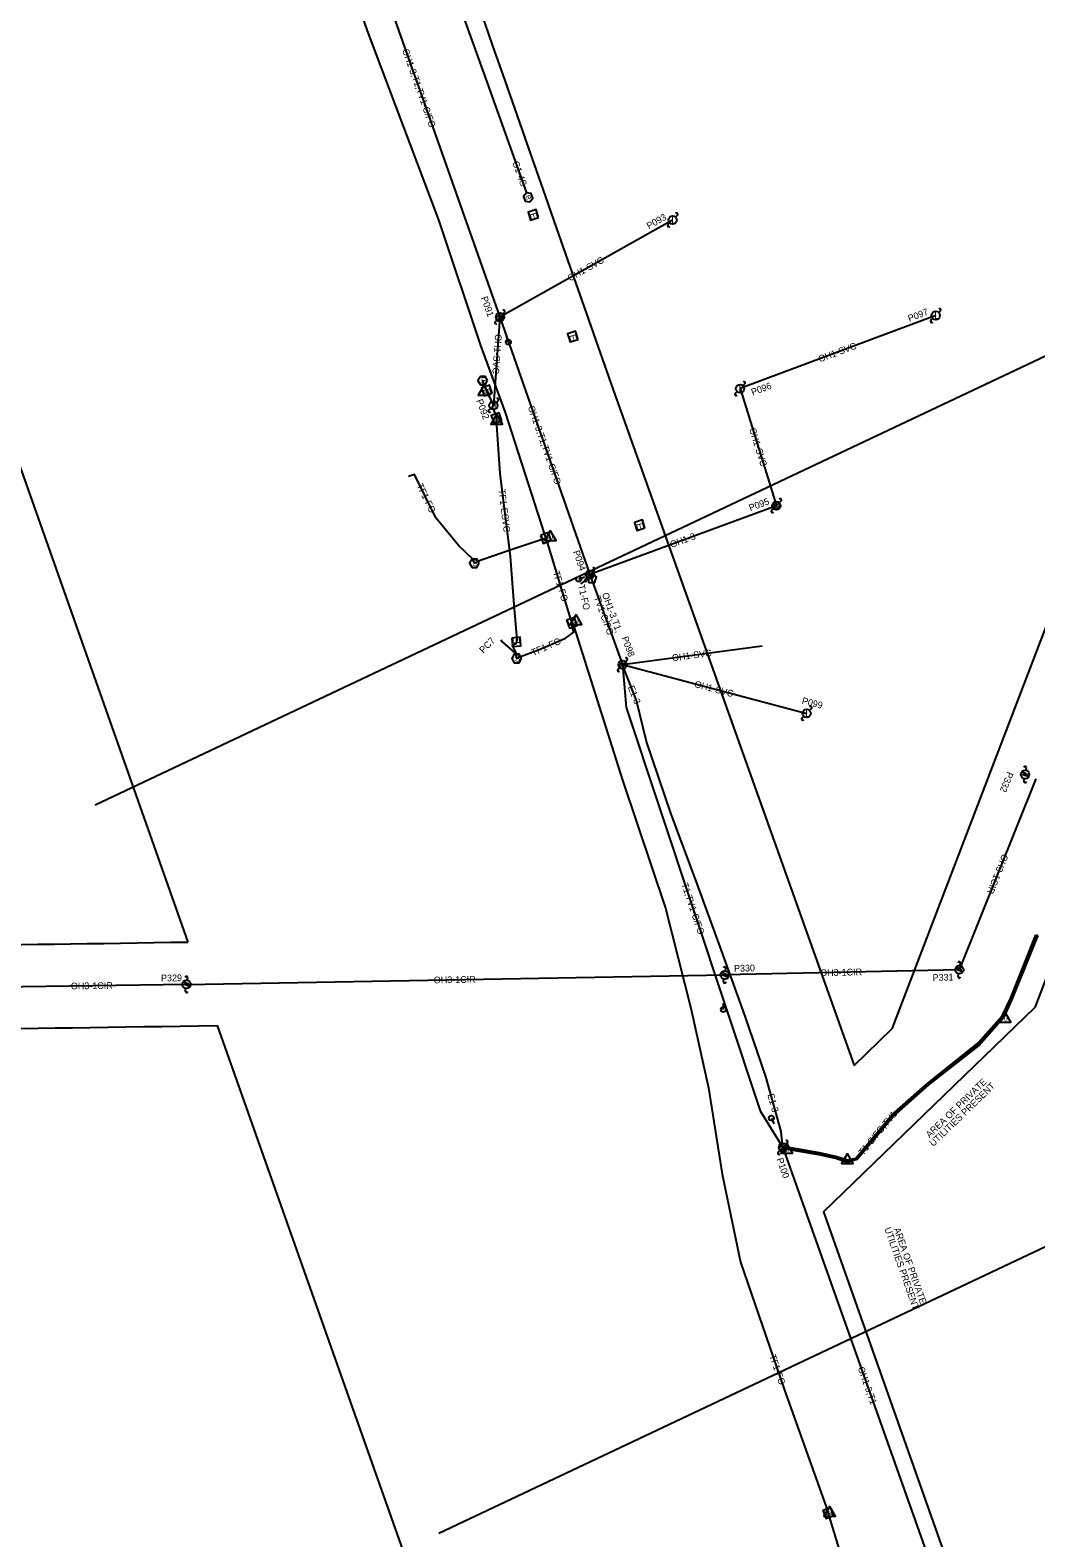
# Model space of a CAD drawing. Extents: x 1991878 to 2008544, y 770238 to 1141211.
# Drawn here: x 2005581 to 2006181, y 1137047 to 1137946 of the extents above; entities that cross this region are included whole.
import ezdxf

# ---------------------------------------------------------------- set-up
doc = ezdxf.new("R2010")
doc.units = 0
for name, color, linetype in [('RD_EX_SU_Elec', 7, 'Continuous'), ('RD_EX_SU_Gas', 7, 'Continuous'), ('RD_EX_SU_Misc', 7, 'Continuous'), ('RD_EX_SU_Ovhd', 7, 'Continuous'), ('RD_EX_SU_Pole', 7, 'Continuous'), ('RD_EX_SU_SwpLmt', 7, 'Continuous'), ('RD_EX_SU_Telecom', 7, 'Continuous'), ('RD_EX_SU_Trfc', 7, 'Continuous'), ('RD_EX_SU_TX_Elec', 7, 'Continuous'), ('RD_EX_SU_TX_Gas', 7, 'Continuous'), ('RD_EX_SU_TX_Misc', 7, 'Continuous'), ('RD_EX_SU_TX_Ovhd', 7, 'Continuous'), ('RD_EX_SU_TX_Pole', 7, 'Continuous'), ('RD_EX_SU_TX_Telecom', 7, 'Continuous'), ('RD_EX_SU_TX_Trfc', 7, 'Continuous'), ('RD_HC_Cl', 7, 'Continuous')]:
    doc.layers.add(name, color=color, linetype=linetype)

# ---------------------------------------------------------------- blocks, each defined once
blk = doc.blocks.new('GW')
at = {"layer": 'RD_EX_SU_Pole'}
blk.add_line((0, 0), (0, 5), dxfattribs=at)
blk.add_circle((0, 0), 2, dxfattribs=at)

msp = doc.modelspace()

# ---------------------------------------------------------------- linework, layer by layer
at = {"layer": 'RD_EX_SU_Elec'}
for points in [[(2005884.55, 1137834.25), (2005883.1, 1137839.03), (2005878.32, 1137837.59), (2005879.77, 1137832.8)], [(2005908.05, 1137761.71), (2005906.6, 1137766.5), (2005901.82, 1137765.05), (2005903.27, 1137760.27)], [(2005854.13, 1137737.14), (2005852.69, 1137739.63), (2005849.8, 1137739.63), (2005848.36, 1137737.14), (2005849.8, 1137734.64), (2005852.69, 1137734.64)], [(2005856.85, 1137729.6), (2005855.21, 1137734.32), (2005850.49, 1137732.68), (2005852.13, 1137727.96)], [(2005862.67, 1137713.21), (2005861.03, 1137717.93), (2005856.31, 1137716.29), (2005857.95, 1137711.57)], [(2005947.98, 1137649.3), (2005946.54, 1137654.09), (2005941.75, 1137652.64), (2005943.2, 1137647.86)], [(2005868.56, 1137583.69), (2005868.98, 1137578.71), (2005873.96, 1137579.13), (2005873.54, 1137584.11)]]:
    msp.add_lwpolyline(points, close=True, dxfattribs=at)
for points in [[(2005851.24, 1137737.14), (2005851.38, 1137736.57), (2005853.08, 1137731.64), (2005853.67, 1137731.14), (2005853.7, 1137730.29), (2005857.16, 1137723.18), (2005857.61, 1137722.35), (2005856.88, 1137721.34), (2005859.2, 1137716.04), (2005859.49, 1137714.75), (2005859.21, 1137713.5), (2005861.45, 1137681.78), (2005867.49, 1137632.27), (2005869.8, 1137603.46), (2005871.55, 1137582.69), (2005871.26, 1137581.41), (2005870.87, 1137580.22), (2005868.76, 1137579.27), (2005871.05, 1137574.94), (2005871.43, 1137571.49)], [(2006030.23, 1137280.03), (2006029.93, 1137281.33), (2006029.09, 1137289.62), (2006020, 1137322.26), (2006007.75, 1137358.28), (2005993.52, 1137397.42), (2005979.03, 1137437.19), (2005963.36, 1137479.35), (2005948.86, 1137522.07), (2005942.96, 1137546.51), (2005934.89, 1137566.81), (2005934.61, 1137567.83)]]:
    msp.add_lwpolyline(points, dxfattribs=at)
at = {"layer": 'RD_EX_SU_Gas'}
msp.add_lwpolyline([(2005837.69, 1137959.33), (2005854.61, 1137912.37), (2005871.82, 1137864.61), (2005877.34, 1137849.07)], dxfattribs=at)
msp.add_lwpolyline([(2005879.27, 1137843.63), (2005881.15, 1137845.83), (2005880.18, 1137848.55), (2005877.34, 1137849.07), (2005875.47, 1137846.87), (2005876.44, 1137844.15)], close=True, dxfattribs=at)
at = {"layer": 'RD_EX_SU_Misc'}
for points in [[(2005852, 1137734.38), (2005848.53, 1137728.38), (2005855.46, 1137728.38)], [(2005859.51, 1137717.1), (2005856.04, 1137711.1), (2005862.97, 1137711.1)], [(2005891.47, 1137647.76), (2005888.01, 1137641.76), (2005894.94, 1137641.76)], [(2005906.85, 1137597.8), (2005903.39, 1137591.8), (2005910.32, 1137591.8)], [(2006162.65, 1137360.82), (2006159.18, 1137354.82), (2006166.11, 1137354.82)], [(2006032.44, 1137282.75), (2006028.98, 1137276.75), (2006035.91, 1137276.75)], [(2006068.69, 1137276.47), (2006065.22, 1137270.47), (2006072.15, 1137270.47)], [(2006058.14, 1137066.23), (2006054.67, 1137060.23), (2006061.6, 1137060.23)]]:
    msp.add_lwpolyline(points, close=True, dxfattribs=at)
at = {"layer": 'RD_EX_SU_Ovhd'}
for p, q in [((2005765.34, 1138046.91), (2005861.45, 1137774.95)), ((2005964.48, 1137832.84), (2005861.45, 1137774.95)), ((2005861.45, 1137774.95), (2005857.61, 1137722.35)), ((2005861.45, 1137774.95), (2005915.09, 1137621.47)), ((2006121.36, 1137775.91), (2006004.67, 1137732.36)), ((2006004.67, 1137732.36), (2006026.31, 1137662.56)), ((2006026.31, 1137662.56), (2005915.09, 1137621.47)), ((2005915.09, 1137621.47), (2005934.61, 1137567.83)), ((2005934.61, 1137567.83), (2006017.9, 1137579.03)), ((2005934.61, 1137567.83), (2006044.4, 1137538.79)), ((2006181.07, 1137499.76), (2006135.42, 1137385.97)), ((2005674.58, 1137377.24), (2005995.53, 1137382.92)), ((2006135.42, 1137385.97), (2005995.53, 1137382.92)), ((2005674.58, 1137377.24), (2005562.69, 1137375.66)), ((2006030.23, 1137280.03), (2006130.7, 1136997.12))]:
    msp.add_line(p, q, dxfattribs=at)
msp.add_lwpolyline([(2005934.61, 1137567.83), (2005936.8, 1137542.22), (2006016.65, 1137301.86), (2006030.23, 1137280.03)], dxfattribs=at)
at = {"layer": 'RD_EX_SU_Pole'}
for p, q in [((2005966.25, 1137834.61), (2005967.31, 1137835.67)), ((2005961.66, 1137830.01), (2005962.72, 1137831.07)), ((2005863.21, 1137776.72), (2005864.27, 1137777.78)), ((2006123.13, 1137777.67), (2006124.19, 1137778.73)), ((2005858.62, 1137772.12), (2005859.68, 1137773.18)), ((2005859.03, 1137774.3), (2005862.09, 1137777.36)), ((2005859.68, 1137773.18), (2005863.21, 1137776.72)), ((2005860.8, 1137772.53), (2005863.86, 1137775.59)), ((2006118.53, 1137773.08), (2006119.59, 1137774.14)), ((2006006.44, 1137734.13), (2006007.5, 1137735.19)), ((2005859.37, 1137724.12), (2005860.43, 1137725.18)), ((2006001.85, 1137729.53), (2006002.91, 1137730.59)), ((2005854.78, 1137719.52), (2005855.84, 1137720.58)), ((2006023.89, 1137661.91), (2006026.95, 1137664.97)), ((2006024.54, 1137660.79), (2006028.07, 1137664.32)), ((2006025.66, 1137660.14), (2006028.72, 1137663.2)), ((2006028.07, 1137664.32), (2006029.13, 1137665.38)), ((2006023.48, 1137659.73), (2006024.54, 1137660.79)), ((2005912.27, 1137618.65), (2005913.33, 1137619.71)), ((2005912.68, 1137620.83), (2005915.74, 1137623.89)), ((2005913.33, 1137619.71), (2005916.86, 1137623.24)), ((2005914.45, 1137619.06), (2005917.51, 1137622.12)), ((2005916.86, 1137623.24), (2005917.92, 1137624.3)), ((2005931.79, 1137565), (2005932.85, 1137566.06)), ((2005932.2, 1137567.19), (2005935.26, 1137570.25)), ((2005932.85, 1137566.06), (2005936.38, 1137569.6)), ((2005933.97, 1137565.42), (2005937.03, 1137568.48)), ((2005936.38, 1137569.6), (2005937.44, 1137570.66)), ((2006041.58, 1137535.97), (2006042.64, 1137537.03)), ((2006046.17, 1137540.56), (2006047.23, 1137541.62)), ((2006173.96, 1137498.4), (2006174.22, 1137499.88)), ((2006175.12, 1137504.8), (2006175.39, 1137506.27)), ((2005995.98, 1137385.38), (2005996.24, 1137386.85)), ((2006134.71, 1137382.04), (2006134.97, 1137383.51)), ((2006135.87, 1137388.43), (2006136.14, 1137389.91)), ((2005673.87, 1137373.3), (2005674.13, 1137374.78)), ((2005675.03, 1137379.7), (2005675.3, 1137381.17)), ((2005994.81, 1137378.98), (2005995.08, 1137380.46)), ((2006027.4, 1137277.2), (2006028.46, 1137278.26)), ((2006027.81, 1137279.38), (2006030.87, 1137282.44)), ((2006028.46, 1137278.26), (2006032, 1137281.8)), ((2006029.58, 1137277.61), (2006032.64, 1137280.68)), ((2006032, 1137281.8), (2006033.06, 1137282.86))]:
    msp.add_line(p, q, dxfattribs=at)
for points in [[(2006173.2, 1137503.77), (2006175.03, 1137502.58), (2006173.37, 1137502.41), (2006176.44, 1137501.27), (2006176.44, 1137501.27), (2006174.26, 1137502.31), (2006175.86, 1137502.44)], [(2005994.06, 1137384.35), (2005995.89, 1137383.16), (2005994.23, 1137382.99), (2005997.3, 1137381.85), (2005997.3, 1137381.85), (2005995.12, 1137382.89), (2005996.71, 1137383.02)], [(2006133.95, 1137387.4), (2006135.78, 1137386.21), (2006134.12, 1137386.04), (2006137.19, 1137384.91), (2006137.19, 1137384.91), (2006135.01, 1137385.95), (2006136.61, 1137386.07)], [(2005673.11, 1137378.67), (2005674.94, 1137377.48), (2005673.28, 1137377.31), (2005676.35, 1137376.17), (2005676.35, 1137376.17), (2005674.17, 1137377.21), (2005675.77, 1137377.34)]]:
    msp.add_lwpolyline(points, close=True, dxfattribs=at)
for centre in [(2005964.48, 1137832.84), (2006121.36, 1137775.91), (2005861.45, 1137774.95), (2006004.67, 1137732.36), (2005857.61, 1137722.35), (2006026.31, 1137662.56), (2005915.09, 1137621.47), (2005934.61, 1137567.83), (2006044.4, 1137538.79), (2006174.67, 1137502.34), (2005995.53, 1137382.92), (2006135.42, 1137385.97), (2005674.58, 1137377.24), (2006030.23, 1137280.03)]:
    msp.add_circle(centre, 2.5, dxfattribs=at)
for centre, start, end in [((2005966.78, 1137836.2), 315.01158, 135.01158), ((2005962.19, 1137829.48), 135.01158, 315.01158), ((2005863.74, 1137778.31), 315.01158, 135.01158), ((2006123.66, 1137779.26), 315.01158, 135.01158), ((2005859.15, 1137771.59), 135.01158, 315.01158), ((2006119.06, 1137772.55), 135.01158, 315.01158), ((2006006.97, 1137735.72), 315.01158, 135.01158), ((2005859.9, 1137725.71), 315.01158, 135.01158), ((2006002.38, 1137729), 135.01158, 315.01158), ((2005855.31, 1137718.99), 135.01158, 315.01158), ((2006028.6, 1137665.92), 315.01158, 135.01158), ((2006024.01, 1137659.2), 135.01158, 315.01158), ((2005917.39, 1137624.83), 315.01158, 135.01158), ((2005912.8, 1137618.11), 135.01158, 315.01158), ((2005936.91, 1137571.19), 315.01158, 135.01158), ((2005932.32, 1137564.47), 135.01158, 315.01158), ((2006042.11, 1137535.43), 135.01158, 315.01158), ((2006046.7, 1137542.15), 315.01158, 135.01158), ((2006174.65, 1137506.41), 349.68899, 169.68899), ((2006174.69, 1137498.27), 169.68899, 349.68899), ((2005995.51, 1137386.99), 349.68899, 169.68899), ((2006135.4, 1137390.04), 349.68899, 169.68899), ((2005674.56, 1137381.31), 349.68899, 169.68899), ((2005995.55, 1137378.85), 169.68899, 349.68899), ((2006135.44, 1137381.9), 169.68899, 349.68899), ((2005674.6, 1137373.17), 169.68899, 349.68899), ((2006032.53, 1137283.39), 315.01158, 135.01158), ((2006027.93, 1137276.67), 135.01158, 315.01158)]:
    msp.add_arc(centre, 0.75, start, end, dxfattribs=at)
at = {"layer": 'RD_EX_SU_SwpLmt'}
for p, q in [((2005030.01, 1139228.23), (2005675.36, 1137402.49)), ((2006541.57, 1138517.27), (2006095.16, 1137350.72)), ((2006396.36, 1137927.97), (2006180.36, 1137363.51)), ((2005928.75, 1137732.27), (2006072.69, 1137329)), ((2006054.36, 1137241.77), (2006180.36, 1137363.51)), ((2005692.93, 1137352.77), (2006786.69, 1134258.45)), ((2006072.69, 1137329), (2006095.16, 1137350.72)), ((2006054.36, 1137241.77), (2006432.49, 1136172))]:
    msp.add_line(p, q, dxfattribs=at)
for points in [[(2005533.64, 1138832.03), (2005572.71, 1138741.34), (2005634.23, 1138568.62), (2005740.87, 1138268.93), (2005928.75, 1137732.27)], [(2005029.38, 1137367.89), (2005225.74, 1137395.38), (2005285.84, 1137396.55), (2005358.1, 1137397.97), (2005567.61, 1137400.8), (2005675.36, 1137402.49)], [(2005046.71, 1137319.82), (2005231.01, 1137345.47), (2005288.28, 1137346.59), (2005359.52, 1137347.99), (2005574.44, 1137350.89), (2005692.93, 1137352.77)]]:
    msp.add_open_spline(points, degree=3, dxfattribs=at)
for points in [[(2004646.84, 1138135.19), (2004687.52, 1138023.2), (2004923.72, 1137366.12), (2005034.36, 1137059.95), (2005190.27, 1136632.11), (2005397.95, 1136061.46), (2006006.55, 1134389.96)], [(2005046.71, 1137319.82), (2005128.36, 1137094.06), (2005284.23, 1136666.33), (2005491.91, 1136095.67), (2006159.4, 1134262.44)]]:
    msp.add_spline(points, degree=3, dxfattribs=at)
at = {"layer": 'RD_EX_SU_Telecom'}
msp.add_lwpolyline([(2005916.31, 1137622.29), (2005913.45, 1137620.21), (2005914.54, 1137616.86), (2005918.07, 1137616.86), (2005919.16, 1137620.21)], close=True, dxfattribs=at)
for points in [[(2005915.09, 1137621.47), (2005915.7, 1137620.79), (2005916.16, 1137619.73), (2005916.31, 1137619.29)], [(2006030.23, 1137280.03), (2006031.67, 1137280.05), (2006051.76, 1137276.46), (2006062.3, 1137274.07), (2006068.2, 1137272.06), (2006074.01, 1137273.42), (2006095.43, 1137299.2), (2006116.9, 1137317.86), (2006146.71, 1137341.48), (2006161.85, 1137358.13), (2006166.8, 1137369.09), (2006181.96, 1137407.04)], [(2006030.23, 1137280.03), (2006031.46, 1137280.61), (2006051.9, 1137277.09), (2006062.45, 1137274.68), (2006068.68, 1137272.68), (2006073.65, 1137273.7), (2006095.23, 1137299.48), (2006116.62, 1137318.35), (2006146.46, 1137342.26), (2006161.06, 1137358.48), (2006166.04, 1137368.82), (2006181.11, 1137406.8)], [(2006030.23, 1137280.03), (2006031.63, 1137279.3), (2006051.45, 1137275.79), (2006062.18, 1137273.47), (2006068.62, 1137271.23), (2006074.47, 1137273.07), (2006095.88, 1137298.54), (2006117.28, 1137317.44), (2006147.3, 1137340.87), (2006162.26, 1137357.68), (2006166.96, 1137368.2), (2006182.46, 1137406.49)]]:
    msp.add_lwpolyline(points, dxfattribs=at)
at = {"layer": 'RD_EX_SU_Trfc'}
for points in [[(2005743.3, 1138057.7), (2005782.38, 1137945.64), (2005825.12, 1137832.3), (2005849.84, 1137758), (2005864.53, 1137718.03), (2005887.98, 1137645.42), (2005888.85, 1137643.3), (2005889.07, 1137642.7), (2005903.59, 1137594.88), (2005904.41, 1137592.74), (2005905.49, 1137590.66), (2005934.65, 1137499.05), (2005960.14, 1137422.71), (2005975.34, 1137363.11), (2005985.84, 1137315.59), (2005994, 1137264.09), (2006004.91, 1137211.63), (2006030.93, 1137135.98), (2006056.95, 1137063.16), (2006057.27, 1137062.1), (2006057.69, 1137060.59), (2006069.35, 1137022.2)], [(2005888.85, 1137643.3), (2005887.3, 1137642.62), (2005867.04, 1137635.82), (2005847.53, 1137629.01), (2005846.31, 1137628.25), (2005845.15, 1137630.94), (2005836.93, 1137638.62), (2005823.24, 1137655.33), (2005810.63, 1137681.24), (2005807.05, 1137679.88)], [(2005861.93, 1137582.6), (2005862.64, 1137581.65), (2005870.63, 1137574.68), (2005871.43, 1137571.49), (2005872.77, 1137572.19), (2005884.55, 1137576.59), (2005900.53, 1137583.59), (2005905.54, 1137587.1), (2005904.65, 1137590.46), (2005904.41, 1137592.74)]]:
    msp.add_lwpolyline(points, dxfattribs=at)
for points in [[(2005885.67, 1137644.84), (2005887.32, 1137640.12), (2005892.04, 1137641.77), (2005890.39, 1137646.49)], [(2005849.19, 1137628.25), (2005847.75, 1137630.75), (2005844.86, 1137630.75), (2005843.42, 1137628.25), (2005844.86, 1137625.75), (2005847.75, 1137625.75)], [(2005901.21, 1137594.26), (2005902.89, 1137589.55), (2005907.6, 1137591.22), (2005905.92, 1137595.93)], [(2005874.31, 1137571.49), (2005872.87, 1137573.99), (2005869.98, 1137573.99), (2005868.54, 1137571.49), (2005869.98, 1137568.99), (2005872.87, 1137568.99)]]:
    msp.add_lwpolyline(points, close=True, dxfattribs=at)
at = {"layer": 'RD_EX_SU_TX_Telecom'}
for p, q in [((2005909.64, 1137615.94), (2005915.93, 1137620.26)), ((2005915.7, 1137620.79), (2005915.7, 1137620.79))]:
    msp.add_line(p, q, dxfattribs=at)
at = {"layer": 'RD_EX_SU_TX_Trfc'}
msp.add_lwpolyline([(2006054.08, 1137063.62), (2006055.75, 1137058.91), (2006060.46, 1137060.58), (2006058.79, 1137065.29)], close=True, dxfattribs=at)
at = {"layer": 'RD_HC_Cl'}
for p, q in [((2006328.44, 1137818.67), (2005620.01, 1137484.06)), ((2006533.44, 1137384.65), (2005825.01, 1137050.04))]:
    msp.add_line(p, q, dxfattribs=at)

# ---------------------------------------------------------------- block references
at = {"layer": 'RD_EX_SU_Pole'}
for p, xscale, yscale, rotation in [((2005866.55, 1137760.08), 0.75, 0.7499999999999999, 18.952317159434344), ((2005908.47, 1137618.83), 0.7500000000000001, 0.7499999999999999, -68.22244139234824), ((2005994.69, 1137362.23), 0.75, 0.75, -2.328156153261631), ((2006023.38, 1137297.55), 0.7500000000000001, 0.7499999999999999, -158.6613229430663)]:
    msp.add_blockref('GW', p, dxfattribs=dict(at, xscale=xscale, yscale=yscale, rotation=rotation))

# ---------------------------------------------------------------- texts
at = {"layer": 'RD_EX_SU_Elec'}
for rotation, p in [(286.82887, (2005879.17, 1137836.5)), (286.82887, (2005902.67, 1137763.96)), (289.14431, (2005851.38, 1137731.63)), (289.14431, (2005857.21, 1137715.24)), (286.82887, (2005942.6, 1137651.55)), (94.80587, (2005873.36, 1137580.37))]:
    msp.add_text('E', height=4, rotation=rotation, dxfattribs=at).set_placement(p)
msp.add_text('E', height=3.75, dxfattribs=at).set_placement((2005850.11, 1137735.26))
at = {"layer": 'RD_EX_SU_Gas'}
msp.add_text('e', height=3.75, rotation=289.55498, dxfattribs=at).set_placement((2005876.54, 1137847.12))
at = {"layer": 'RD_EX_SU_Misc'}
for p in [(2005851.24, 1137729.18), (2005858.75, 1137711.9), (2005890.72, 1137642.56), (2005906.1, 1137592.6), (2006161.89, 1137355.62), (2006031.69, 1137277.55), (2006067.93, 1137271.27), (2006057.38, 1137061.03)]:
    msp.add_text('U', height=2.4, dxfattribs=at).set_placement(p)
at = {"layer": 'RD_EX_SU_Pole'}
for s, p in [('L', (2005963.67, 1137830.9)), ('L', (2006120.55, 1137773.97)), ('L', (2006003.86, 1137730.43)), ('m', (2005856.42, 1137721.02)), ('L', (2006043.59, 1137536.86))]:
    msp.add_text(s, height=4, rotation=0.01158, dxfattribs=at).set_placement(p)
at = {"layer": 'RD_EX_SU_Telecom'}
msp.add_text('T', height=3.75, dxfattribs=at).set_placement((2005915.08, 1137617.06))
at = {"layer": 'RD_EX_SU_Trfc'}
for rotation, p in [(109.26758, (2005891.11, 1137642.89)), (109.55103, (2005906.67, 1137592.34))]:
    msp.add_text('F', height=4, rotation=rotation, dxfattribs=at).set_placement(p)
for p in [(2005845.22, 1137626.48), (2005870.34, 1137569.72)]:
    msp.add_text('S', height=3.53, dxfattribs=at).set_placement(p)
at = {"layer": 'RD_EX_SU_TX_Elec'}
for rotation, p in [(291.69329, (2005937.68, 1137554.42)), (285.55507, (2006020.94, 1137311.52))]:
    msp.add_text('E1-3', height=4, rotation=rotation, dxfattribs=at).set_placement(p)
at = {"layer": 'RD_EX_SU_TX_Gas'}
msp.add_text('G1-4S', height=4, rotation=289.55498, dxfattribs=at).set_placement((2005868.78, 1137867.23))
at = {"layer": 'RD_EX_SU_TX_Misc'}
for s, rotation, p in [('AREA OF PRIVATE', 44.01385, (2006117.71, 1137285.45)), ('UTILITIES PRESENT', 44.01385, (2006119.9, 1137280.32)), ('UTILITIES PRESENT', 289.48371, (2006090.68, 1137231.64)), ('AREA OF PRIVATE', 289.48371, (2006096.26, 1137231.5))]:
    msp.add_text(s, height=4, rotation=rotation, dxfattribs=at).set_placement(p)
at = {"layer": 'RD_EX_SU_TX_Ovhd'}
for s, rotation, p in [('OH1-3,T1,TV1-C/FO', 289.46321, (2005803.1, 1137934.06)), ('OH1-SVC', 29.32907, (2005903.26, 1137796.15)), ('OH1-SVC', 265.82529, (2005858.63, 1137764.94)), ('OH1-SVC', 20.4643, (2006052.23, 1137747.97)), ('OH1-3,T1,TV1-C/FO', 289.26758, (2005878.05, 1137721.37)), ('OH1-SVC', 287.21876, (2006010.04, 1137708.29)), ('OH1-3', 20.27436, (2005963.78, 1137637.33)), ('TV1-C/FO', 289.99648, (2005917.42, 1137607.92)), ('OH1-3,T1,', 289.99648, (2005922.22, 1137609.95)), ('OH1-SVC', 7.65933, (2005964.37, 1137569.82)), ('OH1-SVC', 345.18464, (2005977.15, 1137554.51)), ('OH3-1CIR', 248.14261, (2006161.07, 1137455.29)), ('T1,TV1-C/FO', 288.37742, (2005969.64, 1137437.02)), ('OH3-1CIR', 1.25001, (2006052.49, 1137382.16)), ('OH3-1CIR', 0.81022, (2005605.63, 1137374.26)), ('OH3-1CIR', 1.01402, (2005822.06, 1137377.85)), ('OH1-3,T1', 289.55103, (2006074.78, 1137148.59))]:
    msp.add_text(s, height=4, rotation=rotation, dxfattribs=at).set_placement(p)
at = {"layer": 'RD_EX_SU_TX_Pole'}
for s, rotation, p in [('P093', 29.32907, (2005950.36, 1137827.25)), ('P091', 289.46321, (2005850.12, 1137786.5)), ('P097', 20.4643, (2006105.65, 1137772.12)), ('P096', 20.4643, (2006012.18, 1137728.14)), ('P092', 290.69107, (2005847.24, 1137725.19)), ('P095', 20.27436, (2006010.82, 1137659.23)), ('P094', 289.26758, (2005904.98, 1137635.12)), ('PC7', 44.99935, (2005851.59, 1137574.32)), ('P098', 289.99648, (2005934, 1137583.82)), ('P099', 345.18464, (2006041.23, 1137544.64)), ('P332', 248.14272, (2006164.14, 1137504.31)), ('P329', 0.81022, (2005659.39, 1137379.01)), ('P330', 1.01402, (2006001.1, 1137384.82)), ('P331', 1.25001, (2006119.52, 1137379.32)), ('P100', 289.55103, (2006026.36, 1137273.06))]:
    msp.add_text(s, height=4, rotation=rotation, dxfattribs=at).set_placement(p)
at = {"layer": 'RD_EX_SU_TX_Telecom'}
for s, rotation, p in [('T1-FO', 282.84229, (2005908, 1137615.13)), ('T1-C/FO,TV1', 50.26006, (2006077.98, 1137275.03))]:
    msp.add_text(s, height=4, rotation=rotation, dxfattribs=at).set_placement(p)
at = {"layer": 'RD_EX_SU_TX_Trfc'}
for s, rotation, p in [('TF1-FO', 295.94045, (2005811.66, 1137674.59)), ('TF1-ESVC', 276.95836, (2005860.62, 1137672.23)), ('TF1-FO', 286.89561, (2005892.98, 1137622.99)), ('TF1-FO', 23.66077, (2005881.26, 1137572.94)), ('TF1-FO', 288.98345, (2006022, 1137155.86)), ('F', 109.55103, (2006059.54, 1137061.7))]:
    msp.add_text(s, height=4, rotation=rotation, dxfattribs=at).set_placement(p)

doc.saveas('drawing.dxf')
